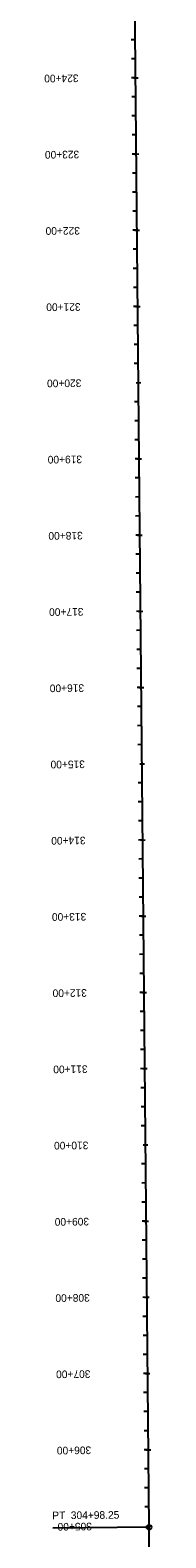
# Model space of a CAD drawing. Extents: x 23417911 to 23421158, y 6737892 to 6791804.
# Drawn here: x 23418122 to 23418262, y 6756965 to 6758944 of the extents above; entities that cross this region are included whole.
import ezdxf

# ---------------------------------------------------------------- set-up
doc = ezdxf.new("R2010")
doc.units = 0
for name, color, linetype in [('Alignment', 7, 'Continuous'), ('TextAlignment', 7, 'Continuous'), ('TextAlignmentLrg', 7, 'Continuous'), ('TextAlignmentSml', 7, 'Continuous')]:
    doc.layers.add(name, color=color, linetype=linetype)

msp = doc.modelspace()

# ---------------------------------------------------------------- linework, layer by layer
at = {"layer": 'Alignment'}
for q in [(23418223.8, 6760759.2), (23418223.8, 6760759.2), (23418223.8, 6760758.6)]:
    msp.add_line((23418258.6, 6756979.4), q, dxfattribs=at)
msp.add_arc((23386716.3, 6756689), 31543.7, 358.71097, 0.52737, dxfattribs=at)
msp.add_arc((23386716.3, 6756689), 31543.7, 358.71097, 0.52737, dxfattribs=at)
at = {"layer": 'TextAlignment'}
for p in [(23418258.6, 6756979.4), (23418132.6, 6756978.2)]:
    msp.add_line(p, (23418132.6, 6756978.2), dxfattribs=at)
msp.add_circle((23418258.6, 6756979.4), 3.12, dxfattribs=at)
at = {"layer": 'TextAlignmentLrg'}
for p, q in [((23418241.1, 6758881), (23418235.7, 6758881)), ((23418242, 6758781), (23418236.6, 6758781)), ((23418243, 6758681), (23418237.5, 6758681)), ((23418243.9, 6758581), (23418238.4, 6758581)), ((23418241.7, 6758481), (23418247.9, 6758481.1)), ((23418245.7, 6758381.1), (23418240.3, 6758381)), ((23418246.6, 6758281.1), (23418241.2, 6758281)), ((23418247.6, 6758181.1), (23418242.1, 6758181)), ((23418248.5, 6758081.1), (23418243, 6758081)), ((23418246.4, 6757981), (23418252.5, 6757981.1)), ((23418250.3, 6757881.1), (23418244.9, 6757881)), ((23418251.3, 6757781.1), (23418245.8, 6757781)), ((23418252.2, 6757681.1), (23418246.7, 6757681)), ((23418253.1, 6757581.1), (23418247.6, 6757581)), ((23418251, 6757481.1), (23418257.1, 6757481.1)), ((23418254.9, 6757381.1), (23418249.5, 6757381)), ((23418255.9, 6757281.1), (23418250.4, 6757281)), ((23418256.8, 6757181.1), (23418251.3, 6757181.1)), ((23418257.7, 6757081.1), (23418252.2, 6757081.1)), ((23418255.6, 6756981.1), (23418261.7, 6756981.1))]:
    msp.add_line(p, q, dxfattribs=at)
at = {"layer": 'TextAlignmentSml'}
for p, q in [((23418240.7, 6758931), (23418235.2, 6758931)), ((23418240.9, 6758906), (23418235.4, 6758906)), ((23418238.1, 6758881), (23418244.2, 6758881.1)), ((23418241.4, 6758856), (23418235.9, 6758856)), ((23418241.6, 6758831), (23418236.1, 6758831)), ((23418241.8, 6758806), (23418236.4, 6758806)), ((23418239, 6758781), (23418245.1, 6758781.1)), ((23418242.3, 6758756), (23418236.8, 6758756)), ((23418242.5, 6758731), (23418237, 6758731)), ((23418242.7, 6758706), (23418237.3, 6758706)), ((23418239.9, 6758681), (23418246, 6758681.1)), ((23418243.2, 6758656), (23418237.7, 6758656)), ((23418243.4, 6758631), (23418238, 6758631)), ((23418243.7, 6758606), (23418238.2, 6758606)), ((23418240.8, 6758581), (23418246.9, 6758581.1)), ((23418244.1, 6758556), (23418238.7, 6758556)), ((23418244.3, 6758531), (23418238.9, 6758531)), ((23418244.6, 6758506), (23418239.1, 6758506)), ((23418241.7, 6758481), (23418247.9, 6758481.1)), ((23418245, 6758456), (23418239.6, 6758456)), ((23418245.3, 6758431), (23418239.8, 6758431)), ((23418245.5, 6758406.1), (23418240, 6758406)), ((23418242.7, 6758381), (23418248.8, 6758381.1)), ((23418246, 6758356.1), (23418240.5, 6758356)), ((23418246.2, 6758331.1), (23418240.7, 6758331)), ((23418246.4, 6758306.1), (23418241, 6758306)), ((23418243.6, 6758281), (23418249.7, 6758281.1)), ((23418246.9, 6758256.1), (23418241.4, 6758256)), ((23418247.1, 6758231.1), (23418241.7, 6758231)), ((23418247.3, 6758206.1), (23418241.9, 6758206)), ((23418244.5, 6758181), (23418250.6, 6758181.1)), ((23418247.8, 6758156.1), (23418242.3, 6758156)), ((23418248, 6758131.1), (23418242.6, 6758131)), ((23418248.3, 6758106.1), (23418242.8, 6758106)), ((23418245.4, 6758081), (23418251.6, 6758081.1)), ((23418248.7, 6758056.1), (23418243.3, 6758056)), ((23418249, 6758031.1), (23418243.5, 6758031)), ((23418249.2, 6758006.1), (23418243.7, 6758006)), ((23418246.4, 6757981), (23418252.5, 6757981.1)), ((23418249.6, 6757956.1), (23418244.2, 6757956)), ((23418249.9, 6757931.1), (23418244.4, 6757931)), ((23418250.1, 6757906.1), (23418244.6, 6757906)), ((23418247.3, 6757881), (23418253.4, 6757881.1)), ((23418250.6, 6757856.1), (23418245.1, 6757856)), ((23418250.8, 6757831.1), (23418245.3, 6757831)), ((23418251, 6757806.1), (23418245.6, 6757806)), ((23418248.2, 6757781), (23418254.3, 6757781.1)), ((23418251.5, 6757756.1), (23418246, 6757756)), ((23418251.7, 6757731.1), (23418246.3, 6757731)), ((23418251.9, 6757706.1), (23418246.5, 6757706)), ((23418249.1, 6757681.1), (23418255.2, 6757681.1)), ((23418252.4, 6757656.1), (23418246.9, 6757656)), ((23418252.6, 6757631.1), (23418247.2, 6757631)), ((23418252.9, 6757606.1), (23418247.4, 6757606)), ((23418250, 6757581.1), (23418256.2, 6757581.1)), ((23418253.3, 6757556.1), (23418247.9, 6757556)), ((23418253.6, 6757531.1), (23418248.1, 6757531)), ((23418253.8, 6757506.1), (23418248.3, 6757506)), ((23418251, 6757481.1), (23418257.1, 6757481.1)), ((23418254.2, 6757456.1), (23418248.8, 6757456)), ((23418254.5, 6757431.1), (23418249, 6757431)), ((23418254.7, 6757406.1), (23418249.2, 6757406)), ((23418251.9, 6757381.1), (23418258, 6757381.1)), ((23418255.2, 6757356.1), (23418249.7, 6757356)), ((23418255.4, 6757331.1), (23418249.9, 6757331)), ((23418255.6, 6757306.1), (23418250.2, 6757306)), ((23418252.8, 6757281.1), (23418258.9, 6757281.1)), ((23418256.1, 6757256.1), (23418250.6, 6757256)), ((23418256.3, 6757231.1), (23418250.9, 6757231.1)), ((23418256.5, 6757206.1), (23418251.1, 6757206.1)), ((23418253.7, 6757181.1), (23418259.8, 6757181.1)), ((23418257, 6757156.1), (23418251.5, 6757156.1)), ((23418257.2, 6757131.1), (23418251.8, 6757131.1)), ((23418257.5, 6757106.1), (23418252, 6757106.1)), ((23418254.6, 6757081.1), (23418260.8, 6757081.1)), ((23418257.9, 6757056.1), (23418252.5, 6757056.1)), ((23418258.2, 6757031.1), (23418252.7, 6757031.1)), ((23418258.4, 6757006.1), (23418252.9, 6757006.1)), ((23418255.6, 6756981.1), (23418261.7, 6756981.1))]:
    msp.add_line(p, q, dxfattribs=at)

# ---------------------------------------------------------------- texts
at = {"layer": 'TextAlignment'}
for s, p in [('PT', (23418131.7, 6756989.9)), ('304+98.25', (23418156, 6756990.1))]:
    msp.add_text(s, height=10.02, rotation=0.5274, dxfattribs=at).set_placement(p)
at = {"layer": 'TextAlignmentLrg'}
for s, p in [('320+00', (23418169.8, 6758485.4)), ('315+00', (23418174.4, 6757985.4)), ('310+00', (23418179, 6757485.4)), ('305+00', (23418183.6, 6756985.4))]:
    msp.add_text(s, height=10.02, rotation=180.5274, dxfattribs=at).set_placement(p)
at = {"layer": 'TextAlignmentSml'}
for s, p in [('324+00', (23418166.1, 6758885.4)), ('323+00', (23418167, 6758785.4)), ('322+00', (23418167.9, 6758685.4)), ('321+00', (23418168.8, 6758585.4)), ('320+00', (23418169.8, 6758485.4)), ('319+00', (23418170.7, 6758385.4)), ('318+00', (23418171.6, 6758285.4)), ('317+00', (23418172.5, 6758185.4)), ('316+00', (23418173.4, 6758085.4)), ('315+00', (23418174.4, 6757985.4)), ('314+00', (23418175.3, 6757885.4)), ('313+00', (23418176.2, 6757785.4)), ('312+00', (23418177.1, 6757685.4)), ('311+00', (23418178, 6757585.4)), ('310+00', (23418179, 6757485.4)), ('309+00', (23418179.9, 6757385.4)), ('308+00', (23418180.8, 6757285.4)), ('307+00', (23418181.7, 6757185.4)), ('306+00', (23418182.7, 6757085.4)), ('305+00', (23418183.6, 6756985.4))]:
    msp.add_text(s, height=10.02, rotation=180.5274, dxfattribs=at).set_placement(p)

doc.saveas('drawing.dxf')
